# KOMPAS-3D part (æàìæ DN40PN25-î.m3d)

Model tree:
1. Объединить компоненты:1  (labels: СЕНС DN40PN25-М)

Referenced files in D:\Савин\!СЕНСОР\3D для заказчика\!Новый перечень\СЕНС\8. СЕНС-М\DN40\: СЕНС DN40PN25-М.a3d
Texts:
  СЕНС DN40PN25-М
  ООО НПП Сенсор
